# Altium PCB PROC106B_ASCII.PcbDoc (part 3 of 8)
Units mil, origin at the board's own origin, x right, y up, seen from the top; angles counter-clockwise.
Board outline 4498.18 x 1060.53 mil, 8 copper layers (Top Layer, GND1, Sig1, PWR1, PWR2, Sig2, GND2, Bottom Layer), stack 69.602 mil thick; 439 components, 327 nets, 1548 pads, 843 vias.
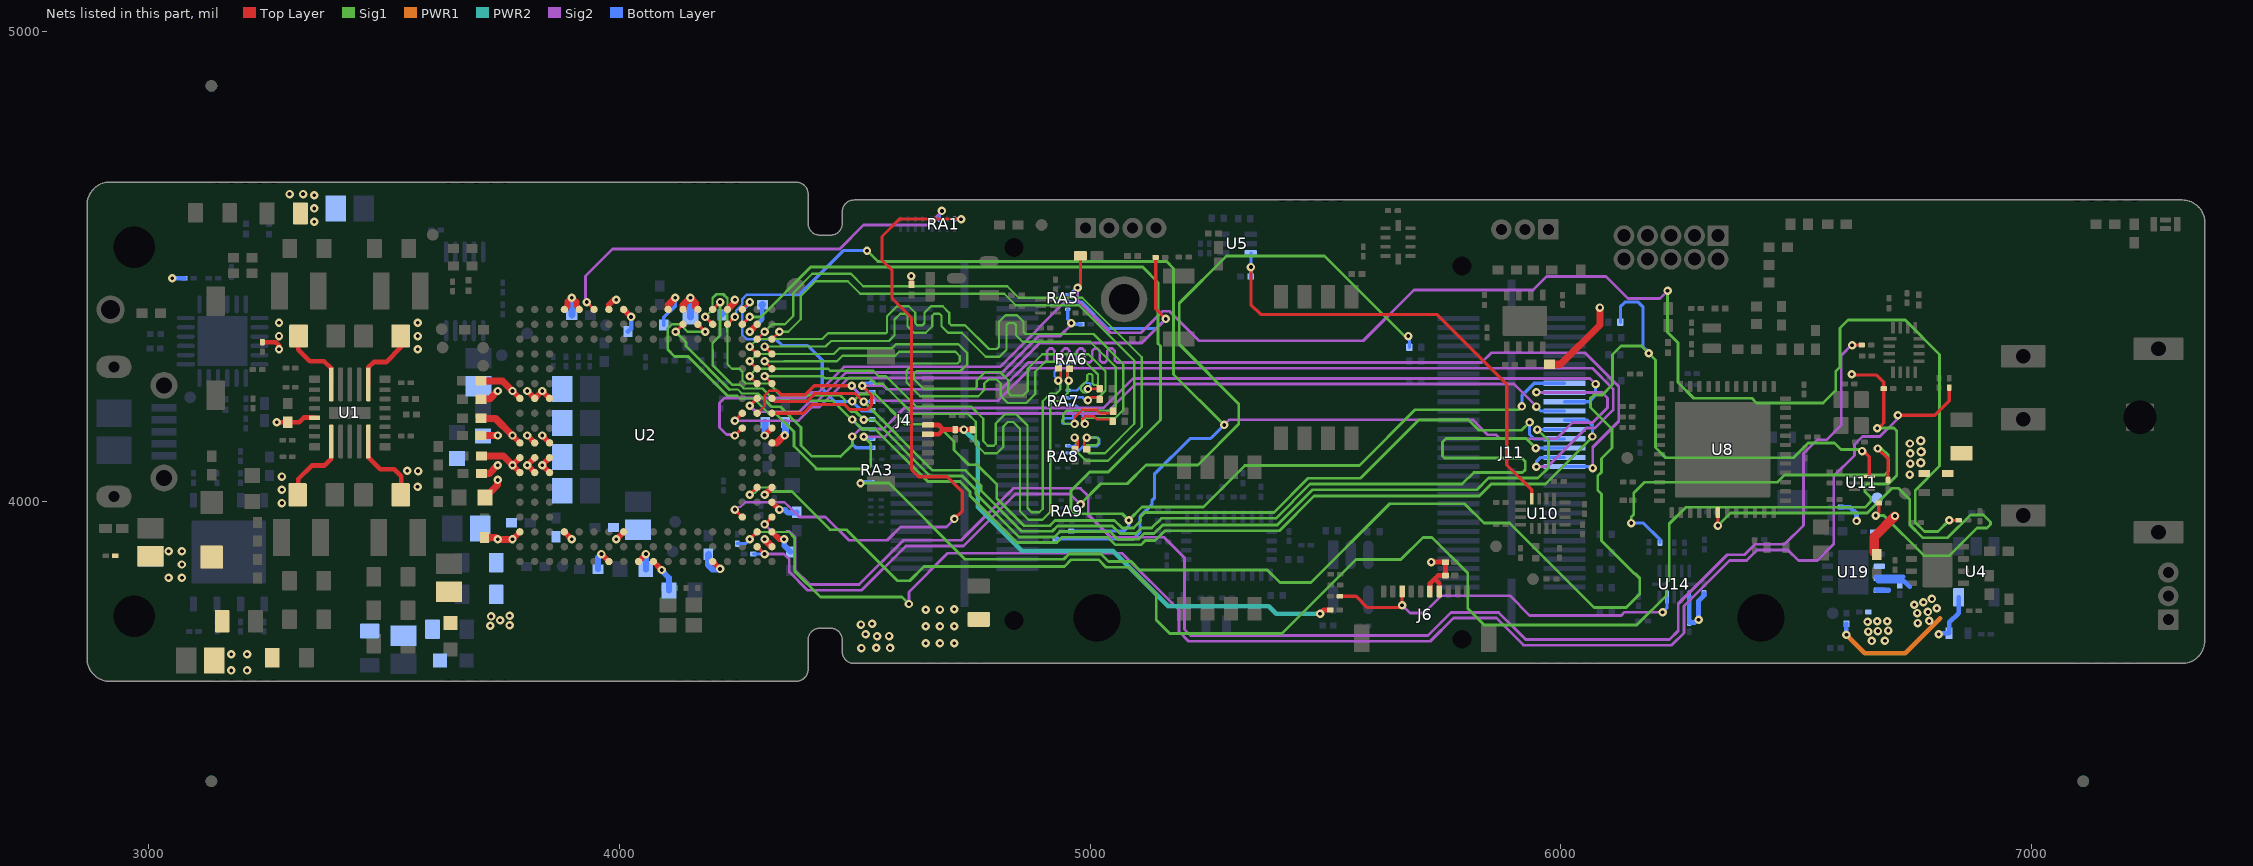
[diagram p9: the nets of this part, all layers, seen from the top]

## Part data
A1: library part CMP-0087189-1, "RF ANT 2.4GHZ CHIP SOLDER SMD"
C1 C4 C50 C51 C52 C53 C55 C59 C62 C65 C70 C76 C78 C82 C112 C113 C121: library part CMP-0008017-2, "CAP, CERM, 10 uF, 10 V, +/- 10%, X7R, 0805"
C2 C3 C91 C92 C101 C126 C130: library part CMP-0006351-2, "CAP, CERM, 0.1 uF, 16 V, +/- 10%, X7R, 0402"
C5 C11 C15 C16 C24 C115 C116 C129: library part CMP-0086446-1, "1µF ±20% 16V Ceramic Capacitor X5R 0201"
C6 C9 C10 C12 C13 C25 C26 C27 C35 C36 C37 C40 C43 C72 C86 C105 C107 C108 C109 C114 C117 C118 C119 C120 C123 C127 C128: library part CMP-0086440-1, "Cap Ceramic 0.1uF 35V X5R 10% Pad SMD 0201 85C T/R"
C7 C42 C122: library part CMP-0006339-4, "CAP, CERM, 10 uF, 10 V, +/- 20%, X5R, 0402"
C8 C125: library part CMP-0086445-1, "CAP CER 10000PF 25V X5R 0201"
C14 C71: library part CMP-0090493-1, "Cap Ceramic 4.7pF 50V C0G 0.25pF Pad SMD 0201 125°C Automotive T/R"
C17 C18: library part CMP-0086441-1, "Cap Ceramic 8pF 50V C0G 0.1pF SMD 0201 125°C Paper T/R"
C19 C20 C38 C39: library part CMP-0087190-1, "CAP CER 12PF 25V C0G/NP0 0201"
C21 C93: library part CMP-0006345-2, "CAP, CERM, 12 pF, 50 V, +/- 5%, C0G/NP0, 0402"
C22 C23 C41: library part CMP-0085178-1, "CAP, CERM, 1 pF, 50 V,+/- 25%, C0G/NP0, AEC-Q200 Grade 1, 0402"
C28 C29: library part CMP-0089043-4, "CAP CER 22UF 6.3V X5R 0402"
C30 C56 C57 C58 C60 C61 C63 C64 C66 C67 C68 C80 C81 C84 C85 C87 C88 C94 C95 C96 C97 C98: library part CMP-0078265-1, "CAP, CERM, 0.22 µF, 16 V,+/- 10%, X7R, AEC-Q200 Grade 1, 0402"
C31 C32 C33 C34: library part CMP-0085511-1, "CAP, CERM, 390 pF, 50 V,+/- 5%, C0G/NP0, AEC-Q200 Grade 1, 0402"
C44 C45 C46 C47 C48 C49 C54 C73 C75 C77 C111 C124 C131: library part CMP-0091983-1, "22µF ±20% 6.3V Ceramic Capacitor X7T 0805 (2012 Metric)"
C69: library part CMP-0006330-2, "CAP, CERM, 0.047 uF, 50 V, +/- 10%, X7R, AEC-Q200 Grade 1, 0402"
C74 C79 C83 C102 C103: library part CMP-0007134-5, "CAP, CERM, 2.2 uF, 6.3 V, +/- 10%, X7R, AEC-Q200 Grade 1, 0603"
C89 C90 C100: library part CMP-0007136-5, "CAP, CERM, 1 uF, 16 V, +/- 10%, X7R, AEC-Q200 Grade 1, 0603"
C99 C104: library part CMP-0086306-1, "CAP, CERM, 1.8 pF, 50 V,+/- 6%, C0G/NP0, 0402"
C106 C110: library part CMP-0006692-2, "CAP, CERM, 4700 pF, 50 V, +/- 10%, X7R, 0402"
D1: library part CMP-0090508-1, "Diode Schottky 30V 2A Surface Mount SOD-123FL"
FID1 FID2 FID3 FID4 FID5 FID6: library part CMP-0077181-1, "Fiducial mark.  There is nothing to buy or mount."
FL2 FL3 FL12 FL22: library part CMP-0078934-1, "Inductor, Ferrite Bead, Ferrite, 2.2 A, 0.035 ohm, AEC-Q200 Grade 1, SMD"
J1: library part CMP-0055293-1, "Connector, Receptacle, Micro-USB Type B, R/A, Bottom Mount SMT"
J2 J11: library part CMP-0075524-1, "Receptacle, 0.5 mm, 30x2, Gold, TH"
J3: library part CMP-0087187-1, "CONN HDR 1.27MM R/A AU 4POS"
J4 J6: library part CMP-0086453-1, "Easy-On™ Type FFC/FPC Connector, Right-Angle, Surface Mount, ZIF, Bottom Contact Style, 1.10mm Mated Height, 10 Circuits"
J5: library part CMP-0081851-1, "DC Power Jack, R/A, TH"
J7: library part CMP-0087786-1, "CONN HEADER R/A 10POS 1.27MM"
J8 J10: library part CMP-0087785-1, "CONN HEADER R/A 3POS 1.27MM"
L1 L6: library part CMP-0058626-1, "Inductor, Multilayer, Air Core, 2.4 nH, 0.3 A, 0.15 ohm, SMD"
L2 L3 L4 L5: library part CMP-0058944-1, "Inductor, Shielded, 470 nH, 4.7 A, 0.021 ohm, SMD"
L7: library part CMP-0062727-1, "Inductor, Multilayer, Ferrite, 6.8 uH, 0.11 A, 0.25 ohm, SMD"
L8: library part CMP-0003349-2, "Ferrite Bead, 1500 ohm @ 100 MHz, 0.5 A, 0603"
L9 L10: library part CMP-0058624-1, "Inductor, Multilayer, Air Core, 2 nH, 0.3 A, 0.1 ohm, SMD"
L11 L13 L15 L16: library part CMP-0089947-1, "100 Ohms @ 100MHz 1 Power Line Ferrite Bead 0805 (2012 Metric) 4A 20mOhm"
L12 L14: library part CMP-0077879-1, "Ferrite Bead, 120 ohm @ 100 MHz, 1.9 A, 0603"
LD1 LD2 LD3 LD4 LD5 LD6: library part CMP-0067682-2, "LED, Green, SMD"
Q1: library part CMP-0087176-1, "MOSFET N-CH 100V 170MA SOT23-3"
R1 R18 R20 R77 R78 R80 R81 R82 R93 R94 R95 R96 R98 R104 R110 R118 R122 R124 R125 R134 R177 R178: library part CMP-0088002-1, "10 kOhms ±0.5% 0.05W, 1/20W Chip Resistor 0201 (0603 Metric)  Thin Film"
R2 R28 R31 R32 R41 R60 R61 R62 R63 R103: library part CMP-0065361-1, "RES, 0, 5%, .05 W, AEC-Q200 Grade 0, 0201"
R3 R7 R8 R19 R21 R22 R23 R35 R36 R43 R44 R45 R59 R65 R83 R84 R85: library part CMP-0090084-1, "RES SMD 10K OHM 0.1% 1/20W 0201"
R4 R5 R9 R37: library part CMP-0090298-1, "100 kOhms ±1% 0.05W, 1/20W Chip Resistor 0201 (0603 Metric) Automotive AEC-Q200 Thick Film"
R6 R46 R47 R48 R49: library part CMP-0089575-2, "Res Thick Film 0201 33.2 Ohm 1% 0.05W(1/20W) ±200ppm/C Pad SMD Automotive T/R"
R10 R11 R88 R130 R132 R133 R135 R137 R138 R140: library part CMP-0087185-1, "RES SMD 20 OHM 1% 1/20W 0201"
R12 R14 R30 R51 R57 R58 R66 R67 R68 R70 R71 R72 R73 R74 R76 R86 R87 R90 R91 R97 R99 R100 R101 R102 R105 R106 R112 R113 R115 R116 R120 R121 R123 R127 R128 R129 R131 R136 R139 R142 R143 R144 R145 R146 R147 R148 R149 R150 R151 R152 R153 R154 R155 R157 R160 R161 R166 R168 R182 R183 R184 R185 R186 R187 R188 R189 R190: library part CMP-0086442-2, "RES SMD 0 OHM JUMPER 1/20W 0201"
R13 R17 R42 R111: library part CMP-0027072-1, "RES, 220, 5%, 0.05 W, 0201"
R15: library part CMP-0090501-1, "220 Ohms ±5% 0.05W, 1/20W Chip Resistor 0201 (0603 Metric) Automotive AEC-Q200 Thick Film"
R16: library part CMP-0027880-1, "RES, 7.87 k, 1%, 0.05 W, 0201"
R24: library part CMP-0087183-1, "RES SMD 200 OHM 1% 1/5W 0402"
R25 R26 R33 R34 R40 R64: library part CMP-0090497-1, "4.99 kOhms ±1% 0.05W, 1/20W Chip Resistor 0201 (0603 Metric) Automotive AEC-Q200 Thick Film"
R27 R107 R108: library part CMP-0027137-1, "RES, 510, 5%, 0.05 W, 0201"
R29 R89 R92: library part CMP-0027261-3, "RES, 100 k, 1%, 0.05 W, 0201"
R38 R69 R141: library part CMP-0027745-1, "RES, 4.99 k, 1%, 0.05 W, 0201"
R39: library part CMP-0090502-1, "510 Ohms ±5% 0.05W, 1/20W Chip Resistor 0201 (0603 Metric) Automotive AEC-Q200 Thick Film"
R50 R75: library part CMP-0090500-1, "1 kOhms ±5% 0.05W, 1/20W Chip Resistor 0201 (0603 Metric) Automotive AEC-Q200 Thick Film"
R52: library part CMP-0090496-1, "Res Thick Film 0201 1.96K Ohm 1% 1/20W 200ppm/C Molded SMD T/R"
R53 R54 R55 R56: library part CMP-0026363-2, "RES, 3.83, 1%, 0.063 W, AEC-Q200 Grade 0, 0402"
R79 R180 R181: library part CMP-0087184-1, "RESISTOR, 0201, 0.05W, 1%, 4K7"
R114 R117 R119 R126: library part CMP-0026491-2, "RES, 61.9, 1%, 0.063 W, AEC-Q200 Grade 0, 0402"
R158 R170 R172: library part CMP-0090499-1, "Res Thick Film 0201 82.5K Ohm 1% 1/20W ±200ppm/°C Molded SMD SMD T/R"
R159 R171: library part CMP-0090503-1, "Res Thick Film 0201 750 Ohm 5% 0.05W(1/20W) ±200ppm/C Pad SMD Automotive T/R"
R174 R176: library part CMP-0090498-1, "Res Thick Film 0201 7.87K Ohm 1% 1/20W ±200ppm/°C Molded SMD SMD T/R"
RA1 RA2 RA3 RA4 RA5 RA6 RA7 RA8 RA9: library part CMP-0087186-1, "RES ARRAY 4 RES ZERO OHM 0502"
S1 S2: library part CMP-0002128-2, "Switch, Slide, SPST 4 poles, SMT"
S3: library part CMP-0087181-1, "SWITCH SLIDE DIP SPST 100MA 6V"
SW2 SW3: library part CMP-0002150-2, "SWITCH TACTILE SPST-NO 0.05A 12V"
TP2 TP3 TP4 TP5 TP6 TP7 TP8 TP9 TP10 TP12 TP13 TP14 TP15 TP16 TP17 TP18 TP19 TP26 TP27 TP46: library part CMP-0078143-3, "TEST POINT.  No entry in BOM."
TP11: library part CMP-0003825-1, "1mm Test Point, SMT"
TP20: library part CMP-0086474-1, "PC Test Point, Loop Brass, Tin Plating 0.047\" (1.19mm) Hole Diameter Mounting Type"
U1: library part CMP-0079120-2, "4-A + 2.5-A + Two 1.5-A Buck Converters With Integrated Switches, RNF0026C (VQFN-HR-26)"
U2: library part CMP-0090288-2
U3: library part CMP-0087172-1, "I/O Controller Interface IC USB to Dual UART bridge"
U4: library part CMP-0035419-1, "Single Output High PSRR LDO, 200 mA, Fixed 3 V Output, 2.7 to 5.5 V Input, 5-pin SOT-23 (DBV), -40 to 85 degC, Green (RoHS & no Sb/Br)"
U5: library part CMP-0067398-2, "Automotive Grade, 1.4V-Capable +/-0.5degC Temperature Sensor with Alert Function and I2C/SMBus, DRL0006A (SOT-OTHER-6)"
U6: library part CMP-0087170-1, "8KB I2C SER EEPROM TSOT 23"
U7: library part CMP-0087171-1, "IMU ACCEL/GYRO/MAG I2C 32BIT"
U8: library part CMP-0083675-2, "SimpleLink(TM) Bluetooth(R) 5 low energy Wireless MCU, RGZ0048A (VQFN-48)"
U9: library part CMP-0079267-1, "2.3V-3.6V, 16M-BIT [x 1/x 2/x 4] CMOS FLASH Memory, WSON-8"
U10: library part CMP-0043349-1, "Low-Voltage 8-Bit I2C and SMBus I/O Expander, 1.65 to 5.5 V, -40 to 85 degC, 16-pin UQFN (RSV), Green (RoHS & no Sb/Br)"
U11: library part CMP-0050992-5, "1-Channel, 2:1 Analog Switch, DSF0006A (X2SON-6)"
U12 U17: library part CMP-0065183-3, "Automotive Fault Protected CAN Transceiver With Flexible Data-Rate, DRB0008F (VSON-8)"
U13: library part CMP-0067415-1, "10-Ohm Quad SPDT Analog Switch, RSV0016A (UQFN-16)"
U14: library part CMP-0860038-1, "Automotive 4-Bit Bidirectional Voltage-Level Translator with Auto Direction Sensing and +/-15kV ESD, RUT0012A (UQFN-12)"
U15: library part CMP-0074545-1, "Dual 10-ohm SPDT Analog Switch, RSE0010A (UQFN-10)"
U16: library part CMP-0087998-2, "AND Gate IC 1 Channel  6-SON (1x1)"
U18: library part CMP-0074341-1, "Automotive Catalog Dual 15-Ohm SPDT Analog Switch, DGS0010A (VSSOP-10)"
U19: library part CMP-0043358-3, "Dual In / Single Out Autoswitching Power Mux, 2.8 to 5.5 V, -40 to 85 degC, 8-pin SON (DRB), Green (RoHS & no Sb/Br)"
Y1: library part CMP-0090505-1, "40MHz ±10ppm Crystal 8pF 50 Ohms 4-SMD, No Lead"
Y2: library part CMP-0088076-1, "48MHz ±20ppm Crystal 7pF 50 Ohms 4-SMD, No Lead"
Y3 Y4: library part CMP-0088006-1, "CRYSTAL 32.768KHZ 4PF SMD"
ZZ1: library part CMP-0003616-3
ZZ2: library part CMP-0077236-1
ZZ3: library part CMP-0077237-1
ZZ4 ZZ5.2: library part CMP-0077238-1
ZZ5.1: library part CMP-0077238-1, "Cut the thermal pad(Part Number#GPVOUS-0.125-AC-0816) for the shape and size of the inner surface of the heatsink(Part Number#160018120021) and paste it on the inner surface of the heatsink;"

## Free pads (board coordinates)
  round 19 hole 24 unplated: ""(3145.41,4687.43) ""(3145.41,3610.9) ""(3175.41,4687.43) ""(3175.41,3610.9) ""(3205.41,4687.43) ""(3205.41,3610.9) ""(3235.41,4687.43) ""(3235.41,3610.9) ""(3265.41,4687.43) ""(3265.41,3610.9) ""(3637.19,4687.43) ""(3637.19,3610.9) ""(3667.19,4687.43) ""(3667.19,3610.9) ""(3697.19,4687.43) ""(3697.19,3610.9) ""(3727.19,4687.43) ""(3727.19,3610.9) ""(3757.19,4687.43) ""(3757.19,3610.9) ""(4128.97,3610.9) ""(4128.97,4687.43) ""(4158.97,3610.9) ""(4158.97,4687.43) ""(4188.97,4687.43) ""(4188.97,3610.9) ""(4218.97,3610.9) ""(4218.97,4687.43) ""(4248.97,3610.9) ""(4248.97,4687.43) ""(4646.5,3648.05) ""(4676.5,3648.05) ""(4706.5,3648.05) ""(4736.5,3648.05) ""(4766.5,3648.05) ""(5409.11,4649.48) ""(5439.11,4649.48) ""(5469.11,4649.48) ""(5499.11,4649.48) ""(5529.11,4649.48) ""(5950.52,3648.05) ""(5980.52,3648.05) ""(6010.52,3648.05) ""(6040.52,3648.05) ""(6070.52,3648.05) ""(7097.6,3648.05) ""(7097.68,4649.43) ""(7127.6,3648.05) ""(7127.68,4649.43) ""(7157.6,3648.05) ""(7157.68,4649.43) ""(7187.6,3648.05) ""(7187.68,4649.43) ""(7217.6,3648.05) ""(7217.68,4649.43)

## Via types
v1: diameter 18, hole 8, Top Layer to Bottom Layer, tented both sides, 804 vias
v2: diameter 19.68, hole 7.87, Top Layer to Bottom Layer, tented both sides, 34 vias
v3: diameter 20, hole 10, Top Layer to Bottom Layer, tented both sides, 3 vias
v4: diameter 18, hole 8, Top Layer to Bottom Layer, 1 vias
v5: diameter 17, hole 7.87, Top Layer to Bottom Layer, 1 vias

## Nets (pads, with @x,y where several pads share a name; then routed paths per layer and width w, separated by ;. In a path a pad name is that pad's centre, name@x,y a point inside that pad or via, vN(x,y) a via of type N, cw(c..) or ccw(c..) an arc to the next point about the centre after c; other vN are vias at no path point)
3V0: C7.1 C15.1 C16.1 C115.1 C116.1 C118.1 J4.6 J4.7 J6.6 J6.7 R79.2 R181.2 U4.5 U14.1 | length 1553.4
  Top Layer w10: J4.7@4655.33,4143.81 4678.32,4143.81 4688.3,4153.79 ; J4.6@4655.33,4163.49 4678.59,4163.49 4688.3,4153.79 ; C15.1@4750.21,4153.69 4750.12,4153.79 v1(4731.8,4153.79) C16.1@4713.47,4153.79 4688.3,4153.79 ; v1(5488.42,3762.4) 5496.67,3770.65 R181.2@5510.03,3770.65 ; J6.6@5721.75,3810.06 5721.75,3826.54 5731.98,3836.77 ; v1@5724.8,3872.26 5724.87,3872.2 C115.1@5754.85,3872.2 C116.1@5754.85,3843.74 5738.95,3843.74 5731.98,3836.77 ; J6.7@5741.43,3807.06 5741.43,3827.32 5731.98,3836.77
  PWR2 w10: v1(4731.8,4153.79) 4761,4124.58 4761,3989.4 4854.25,3896.15 5048.17,3896.15 5165.74,3778.57 5379.01,3778.57 5395.18,3762.4 v1(5488.42,3762.4)
  Bottom Layer w10: U14.1@6272.54,3799.77 6272.54,3764.35 6272.5,3764.32 C118.1@6272.5,3743.88 6284.34,3743.88 6292.44,3751.98 6292.44,3789.79 6304.11,3801.46 R79.2@6304.11,3805.64 ; v1(6802.79,3718.79) 6804.79,3720.79 C7.1@6824.78,3720.79 6824.78,3743.97 6844.78,3763.97 U4.5@6844.78,3797.49
  other v1: 6292.44,3749.79 5724.6,3872.26
5V_HD_IN: C128.1 L16.2 R20.1 U19.8 | length 78.8
  Bottom Layer w10: R20.1@6594.7,3988.94 6614.05,3988.94 6628.05,3974.95 v1(6628.05,3959.58)
  Bottom Layer w12: U19.8@6671.07,3812.08 6695.37,3812.08
  other v1: 4650.94,3699.61 4681.04,3699.61 4711.61,3699.61 6660.22,3704.68 6688.14,3705.36 6652.66,3724.54 6673.29,3725.69 6695.37,3726.86 4650.94,3735.76 4681.04,3735.76 4711.61,3735.76 6651.3,3745.4 6671.76,3746.63 6693.22,3746.68 4650.93,3770.89 4681.04,3771.4 4711.61,3772.13
5V_IN: C1.2 C4.1 C30.1 C50.1 C51.1 C52.1 C53.1 C129.1 D1.1 FL3.2 FL12.2 R27.1 R39.1 R50.2 R64.1 R107.1 U1.9 U1.13 U1.18 U1.22 U1.26 U19.7 | length 1553.7
  Top Layer w10: R50.2@3241.63,4339.44 3270.32,4339.44 3277.02,4332.74 v1@3277.02,4326.81 ; v1(3272.33,4169.32) C30.1@3295.87,4169.32 3319.81,4169.32 3329.65,4179.16 U1.18@3352.68,4179.16 ; C50.1@3318.11,4009.52 3318.11,4048.7 3346.62,4077.21 3373.07,4077.21 3388.04,4092.18 ; C52.1@3318.11,4368.48 3318.11,4323.58 3342.64,4299.04 3372.63,4299.04 3388.11,4283.56 U1.13@3388.11,4249.63 ; 3388.11,4092.18 U1.22@3388.11,4128.37 ; U1.26@3466.85,4128.37 3466.85,4094.45 3492.01,4069.29 3521.99,4069.29 3536.85,4054.43 C51.1@3536.85,4009.52 ; U1.9@3466.85,4249.63 3466.85,4285.9 3478.07,4297.12 3504.66,4297.12 3536.85,4329.31 C53.1@3536.85,4368.48 ; v1(4620.27,4479.75) 4620.57,4479.46 R107.1@4620.57,4461.7
  Top Layer w15: FL12.2@5975.6,4292.41 5999,4292.41 6082.75,4376.16 v1(6082.75,4412.79)
  Top Layer w20: FL3.2@6670.79,3888.25 6665.81,3893.23 6665.81,3926.17 v5(6709.55,3969.91)
  PWR1 w10: v1(6606.39,3717.68) 6645.55,3678.52 6731.31,3678.52 6805.46,3752.67
  Bottom Layer w10: v1(3050.47,4475.15) R64.1@3076.13,4475.15 ; v1(6606.39,3717.68) R27.1@6606.39,3741.52 ; U19.7@6673.76,3836.69 6698.11,3836.69 6703.21,3831.6 ; 6711.81,3839.4 6710.11,3841.1 ; 6726.91,3841.1 6710.11,3841.1 ; 6740.73,3819.94 6729.08,3831.6 6703.21,3831.6 ; 6703.21,3831.6 6673.82,3831.6 6669.11,3840.2 6670.01,3841.1 6710.11,3841.1
  other v1: 4514.3,3689.55 4545.9,3690.22 4574.96,3689.89 4547.43,3714.8 4572.89,3715.13 4522.96,3718.74 4513.24,3739.55 4536.9,3741.13 6757.93,3742.77 6782.31,3747.33 6756.77,3763.83 6779.56,3766.42 6798.43,3774.05 6750.69,3781.76 6770.14,3787.01 6788.19,3794.02 3042.55,3838.89 3070.75,3838.89 3070.75,3867.09 3042.55,3895.28 3070.75,3895.28 3283.23,3997.47 3283.23,4025.66 3571.45,4032.48 3283.23,4053.86 3549.23,4066.35 3572.38,4065.53 3277.02,4324.15 3571.73,4324.15 3277.02,4352.35 3571.73,4352.35 3277.02,4380.54 3571.73,4380.54
5V_IN_B: C42.2 C122.1 C127.1 L15.2 TP4.1 U19.6
  other v1: 6741.2,4058 6741.81,4081.54 6741.81,4103 6741.32,4124.11
  other v3: 6764.6,4082.97 6765.01,4106.67 6764.46,4130
ALERT: R38.1 U5.3 U10.4 | length 1009.2
  Top Layer w6.7: v1(5341.5,4498.97) 5341.5,4418.98 5362.14,4398.33 5736.3,4398.33 5885.05,4249.58 5885.05,4078.41 5937.93,4025.53 U10.4@5937.93,4006.69
  Bottom Layer w6.7: R38.1@5341.5,4478.82 v1(5341.5,4498.97) U5.3@5341.5,4529.03 U5.3@5341.84,4528.69
AR_1P0_RF1: C75.2 C78.1 C79.1 C80.1 C81.1 C113.1 C124.2 L12.2 U2.J16 U2.J17 U2.J18 | length 184.7
  Top Layer w12: v1(3773.02,4141.13) U2.J18@3788.76,4125.38 ; v1(3804.51,4141.13) U2.J17@3820.26,4125.38 ; v1(3836.01,4141.13) U2.J16@3851.76,4125.38
  Top Layer w15: C80.1@3705.88,4141.13 v1(3741.52,4141.13) ; C81.1@3705.88,4177.66 3736.48,4177.66 v1(3773.02,4141.13)
  other v1: 3725.88,3737.02 3766.78,3737.9 3746.66,3748.61 3727.42,3756.7 3766.78,3758.45
AR_1P0_RF2: C70.1 C74.1 C82.1 C83.1 C84.1 C85.1 C111.2 C121.1 C131.2 L14.2 U2.G16 U2.G17 U2.G18 U2.H16 U2.H17 U2.H18 | length 297.2
  Top Layer w12: U2.G18@3788.76,4062.39 v1(3773.02,4078.14) U2.H18@3788.76,4093.88 ; U2.G17@3820.26,4062.39 v1(3804.51,4078.14) U2.H17@3820.26,4093.88 ; U2.G16@3851.76,4062.39 v1(3836.01,4078.14) U2.H16@3851.76,4093.88
  Top Layer w15: C84.1@3707.42,4060.46 3723.84,4060.46 v1(3741.52,4078.14) ; C85.1@3707.42,4097.51 3753.64,4097.51 v1(3773.02,4078.14) ; C74.1@3714.74,4009.15 3741.52,4035.93 v1(3741.52,4046.64)
AR_1P2: C76.1 C91.2 C92.2 C94.1 C95.1 C96.1 C97.1 C98.1 C103.1 L13.2 U2.A5 U2.C1 U2.E1 U2.J1 U2.V4 U2.V6 U2.V7 U2.V8 U2.V12 U2.V14 U2.V15 | length 667.8
  Top Layer w12: U2.V15@3883.25,4408.84 3890,4415.59 3890,4425.59 3899,4434.59 3909,4424.59 3909,4417 3914.75,4411.25 U2.V14@3914.75,4408.84 ; U2.V12@3977.74,4408.84 3977.74,4418.84 3988.49,4429.59 v1(3993.49,4429.59) ; U2.A5@4198.21,3873.41 v1(4213.96,3857.66) ; U2.C1@4324.2,3936.4 4339.94,3920.65 v1(4349.94,3920.65) ; U2.E1@4324.2,3999.4 4324.33,3999.4 v1(4340.08,3983.65)
  Top Layer w15: U2.V8@4103.72,4408.84 4103.72,4418.45 v1(4118.96,4433.68) ; U2.V7@4135.22,4408.84 4135.22,4417.93 v1(4150.97,4433.68) 4161.76,4422.88 4161.76,4413.8 U2.V6@4166.72,4408.84 ; U2.V4@4229.71,4408.84 4245.46,4424.59 v1(4245.46,4429.68) ; U2.J1@4324.2,4125.38 4334.2,4125.38 v1@4350.05,4141.24
  Bottom Layer w8: C96.1@4094.31,4375.82 4094.31,4392.25 4118.96,4416.91 v1(4118.96,4433.68)
  Bottom Layer w10: v1@3898.96,4434.55 v1@3899,4434.59 ; v1(4150.97,4433.68) v1@4150.97,4434.59
  Bottom Layer w12: C91.2@4218.02,4397.33 4245.46,4424.77 v1(4245.46,4429.68) ; v1(4340.08,3983.65) 4351.45,3983.65 4358.24,3976.86 4375.3,3976.86 C95.1@4376.53,3978.09 ; v1@4350,3920 4350,3908 C94.1@4364,3894
  Bottom Layer w15: C98.1@3898.96,4396.76 v1@3898.96,4434.55 ; C103.1@4150.97,4392.63 v1(4150.97,4433.68) ; C97.1@4188.97,3888.79 4189.39,3888.36 4189.39,3866.45 4198.18,3857.66 v1(4213.96,3857.66) ; v1@4350.05,4141.24 4352.69,4143.87 C92.2@4352.69,4168.77
  other v1: 4351.25,4141.24 3899,4433.68 3352.15,4595.26 3352.15,4623.45 3352.15,4651.65 3299.59,4653.99 3328.09,4653.99
AR_1V4_APLL: C90.1 U2.A10 | length 56.1
  Top Layer w12: U2.A10@4040.73,3873.41 v1(4056.48,3889.16)
  Bottom Layer w10: C90.1@4056.23,3855.43 C90.1@4056.48,3855.68
  Bottom Layer w12: C90.1@4056.48,3855.68 v1(4056.48,3889.16)
AR_1V4_SYNTH: C89.1 U2.A9 | length 72
  Top Layer w12: U2.A9@4072.23,3873.41 v1@4087.98,3857.66
  Bottom Layer w12: v1(4090.2,3855.43) 4090.2,3853.81 4105.41,3838.6 C89.1@4105.41,3811.96
AR_1V8: C55.1 C56.1 C57.1 C58.1 C59.1 C60.1 C61.1 C62.1 C63.1 C64.1 C65.1 C66.1 C67.1 C68.1 C73.2 C112.1 L11.2 U2.A12 U2.B1 U2.C11 U2.C15 U2.C18 U2.F1 U2.K1 U2.M16 U2.M17 U2.M18 U2.U2 U2.V11 | length 635.6
  Top Layer w12: v1(3773.02,3920.65) U2.C18@3788.76,3936.4 ; v1(3773.02,4235.62) U2.M18@3788.76,4219.87 ; v1(3804.51,4235.62) U2.M17@3820.26,4219.87 v1(3836.01,4235.62) U2.M16@3851.76,4219.87 ; U2.C15@3883.25,3936.4 v1(3899,3920.65) ; v1(3961.99,3889.16) U2.A12@3977.74,3873.41 ; v1(3993.49,3920.66) U2.C11@4009.24,3936.4 ; U2.V11@4009.24,4408.84 v1(4024.98,4393.1) ; v1(4276.95,4361.6) U2.U2@4292.7,4377.35 ; v1(4308.45,4015.14) U2.F1@4324.2,4030.89 ; v1(4308.45,4141.13) U2.K1@4324.2,4156.88
  Top Layer w15: C58.1@3705.86,4218.19 3724.1,4218.19 v1(3741.52,4235.62) ; C57.1@3705.86,4257.19 3751.44,4257.19 v1(3773.02,4235.62) ; C68.1@3713.57,3924.11 3738.07,3924.11 v1(3741.52,3920.65) v1(3773.02,3920.65) ; v1(4308.45,3920.65) U2.B1@4324.2,3904.91
  Bottom Layer w10: C61.1@4018.33,4361.9 4024.98,4368.55 v1(4024.98,4393.1) ; v1(4276.95,4361.6) 4303.38,4388.02 C56.1@4303.38,4418.18 ; v1(4308.45,4141.13) v1@4309.75,4142.43
  Bottom Layer w12: C63.1@3954.76,3856.83 3954.76,3881.92 v1(3961.99,3889.16)
  Bottom Layer w15: C56.1@4303.38,4418.18 C56.1@4304.26,4419.07 ; v1@4309.75,4142.43 C60.1@4309.75,4168.77
  other v1: 3175.57,3642.06 3209.12,3642.06 3175.57,3676.64 3209.12,3676.64
AR_BSS_LOGGER: RA1.4 U2.D3 | length 1457.8
  Top Layer w6.7: v1(4245.46,3983.65) U2.D3@4261.2,3967.9 ; v1(4711.71,3963.9) 4728.31,3980.49 4728.31,4021.77 4696.67,4053.41 4635.8,4053.41 4620.6,4068.61 4620.6,4390.98 4579.49,4432.09 4579.49,4491.76 4557.8,4513.46 4557.8,4563.91 4594.61,4600.72 4725.6,4600.72 v1(4725.75,4600.58)
  Sig2 w4.5: v1(4245.46,3983.65) 4250.76,3988.95 4256.7,3988.95 4267.15,3999.4 4350.75,3999.4 4358.91,3991.23
  Sig2 w5.95: 4358.91,3991.23 4382.26,3967.89 4438.09,3967.89 4487.48,3918.5 4569.04,3918.5 4597.24,3946.7 4694.51,3946.7 v1(4711.71,3963.9)
  Bottom Layer w6.7: RA1.4@4711.71,4600.58 v1(4725.75,4600.58)
AR_CS1: R9.2 R139.2 U2.C2 | length 3317
  Top Layer w6.7: v1(4276.95,3920.66) U2.C2@4292.7,3936.4 ; v1(6715.81,4184) 6794.11,4184 6824.81,4214.7 R139.2@6824.81,4242.98
  Sig1 w4.5: v1(4276.95,3920.66) 4292.55,3936.25 ; 4292.57,3936.4 4359.48,3936.4 4367.2,3928.68
  Sig1 w5.95: 4367.2,3928.68 4372.68,3923.2 4372.68,3852.89 4427.56,3798 4600.39,3798 v1(4615.19,3783.2)
  Sig2 w5.95: v1(4615.19,3783.2) 4615.19,3808.93 4697.19,3890.93 5068.04,3890.93 5188.57,3770.4 5188.57,3724.39 5208.81,3704.15 5722.57,3704.15 5771.73,3753.31 5862.89,3753.31 5920.43,3695.78 6235.45,3695.78 6261.24,3721.57 6261.24,3778.92 6358.17,3875.85 6394.55,3875.85 6416.88,3898.18 6481.96,3898.18 6504.38,3875.76 6544.85,3875.76 6579.54,3910.44 6579.54,4054.9 6623.31,4098.68 6623.31,4121.75 6640.56,4138.99 6677.31,4138.99 6715.81,4177.5 v1(6715.81,4184)
  Bottom Layer w6.7: R9.2@4250.53,3911.55 4267.85,3911.55 v1(4276.95,3920.66)
AR_CS1_60PIN: R150.2 RA3.1 U11.3 | length 3577.1
  Top Layer w6.7: v1@6639.79,4111.11 6655.07,4095.82 U11.3@6655.07,4054.07
  Sig1 w5.95: v1(4512.23,4039.9) 4572.79,4039.9 4734.57,3878.13 4943.97,3878.13 4955.07,3889.24 5022.69,3889.24 5038.76,3873.16 5087.38,3873.16 5105.13,3855.41 5376.27,3855.41 5403.06,3828.62 5468.8,3828.62 5636.32,3996.14 5795.11,3996.14 5836.32,3954.93 5891.16,3954.93 6070.18,3775.91 6138.83,3775.91 6167.52,3804.59 6167.52,3837.84 6157.87,3847.49 6156.34,3847.49 6086.26,3917.56 6086.26,4017.07 6078.05,4025.28 6078.05,4054.78 6086.26,4062.99 6086.26,4092.5 6108.35,4114.59 6108.35,4155.16 6062.88,4200.64 6062.88,4220.16 6069.96,4227.25 6087.72,4227.25 6109.66,4249.18 6109.66,4313.09 6127.8,4331.24 6171.18,4331.24 v1(6186.75,4315.67) 6200.65,4301.78 6200.65,4115.91 6222.76,4093.79 6494.18,4093.79 6525.34,4124.95 6581.02,4124.95 6594.86,4111.11 v1@6639.79,4111.11
  Bottom Layer w6.7: v1(4512.23,4039.9) 4513.87,4039.9 4517.57,4043.61 RA3.1@4535.95,4043.61 ; R150.2@6126.41,4381.76 6126.41,4414.59 6136.18,4424.36 6164.48,4424.36 6174.21,4414.64 6174.21,4330.28 6186.75,4317.73 v1(6186.75,4315.67)
  other v1: 6639.79,4107.91
AR_CS1_BT: R105.2 U8.30 | length 1081.1
  Top Layer w6.7: v1(6333.54,3949.8) U8.30@6333.54,3977.25 ; v1(6668.81,3971.01) 6675.01,3977.22 R105.2@6675.01,3997.34
  Sig1 w5.95: v1(6333.54,3949.8) 6360.37,3976.64 6650.73,3976.64 6703.16,4029.07 6717.11,4029.07 6740.89,4005.29 6740.89,3951.61 6768.42,3924.08 6821.79,3924.08 6869.97,3972.26 6897.81,3972.26 6912.48,3957.59 6912.48,3951.77 6905.1,3944.39 6884.07,3944.39 6825.56,3885.88 6770.99,3885.88 6685.86,3971.01 v1(6668.81,3971.01)
AR_CS1_LCD: R76.2 R106.2 | length 847.6
  Top Layer w6.7: v1(6673.04,4113.48) 6673.04,4113.33 6695.04,4091.34 R106.2@6695.04,4046.53
  Sig1 w5.95: v4(6149.58,3955.16) 6149.58,3967.73 6154.54,3972.7 6154.54,4018.54 6178,4042 6459.94,4042 6475.03,4057.09 6687.59,4057.09 6695.45,4064.95 6695.45,4099.24 6681.21,4113.48 v1(6673.04,4113.48)
  Bottom Layer w6.7: v4@6150.63,3956.21 v4(6149.58,3955.16) 6174.89,3955.16 6210.78,3919.27 R76.2@6210.78,3913.46
AR_CS1_LCD_T: J6.3 R183.1 U14.4 | length 808.1
  Top Layer w6.7: R183.1@5530.62,3799.62 5564.89,3799.62 5589,3775.51 5662.69,3775.51 v1(5662.69,3780.5) J6.3@5662.69,3810.06
  Sig2 w5.95: v1(5662.69,3780.5) 5679.39,3763.8 5708.98,3763.8 5746.07,3800.89 5891.53,3800.89 5933.37,3759.05 6128.25,3759.05 6135,3765.81 v1(6215.84,3765.81)
  Bottom Layer w6.7: v1(6215.84,3765.81) 6225.29,3775.26 U14.4@6225.29,3797.8
AR_DMM_CLK: J11.15 R11.1 U2.U3 | length 2863.5
  Top Layer w6.7: U2.U3@4261.2,4377.35 v1(4276.95,4393.1)
  Sig1 w5.95: v1(4276.95,4393.1) 4300.77,4393.1 4406.49,4498.81 5111.66,4498.81 5144.37,4466.1 5144.37,4336.15 5149.25,4331.27 5149.25,4174.31 5038.48,4063.54 4999.25,4063.54 4959.53,4023.82 4959.53,3983.93 4968.69,3974.76 5068.35,3974.76 v1(5082.11,3961) 5110.48,3989.37 5240.5,3989.37 5328.59,4077.46 5572.06,4077.46 5690.34,4195.73 5910.11,4195.73 v1(5917.11,4202.74)
  Bottom Layer w6.7: R11.1@4960.02,3937.94 5071.27,3937.94 5082.11,3948.78 v1(5082.11,3961) ; v1(5917.11,4202.74) 5917.11,4225.75 5943.5,4252.14 J11.15@6007.91,4252.14
AR_DMM_SYNC: J11.17 R10.1 U2.U4 | length 3035.4
  Top Layer w6.7: U2.U4@4229.71,4377.35 v1(4245.46,4393.1)
  Sig1 w5.95: v1(4526.01,4533.75) 4549.05,4510.71 5162.64,4510.71 5177.31,4496.03 5177.31,4270.93 v1(5284.75,4163.49)
  Sig2 w5.95: v1(5284.75,4163.49) 5296,4174.75 5811.84,4174.75 5843.88,4142.71 5862.4,4142.71 5871.08,4134.03 5990.13,4134.03 6024.74,4168.63 6067.55,4168.63 6099.07,4200.15 6099.07,4221.06 6087.61,4232.53 5948.46,4232.53 v1(5947.91,4233.07)
  Bottom Layer w5: v1(4245.46,4393.1) 4247.94,4395.58 4247.94,4406.09 4261.2,4419.35 4261.2,4430.66 4261.25,4430.71 4261.25,4431.1 4270.45,4440.29 4287.98,4440.29 4382.34,4440.31 4385,4442.97
  Bottom Layer w5.5: J11.17@6007.91,4232.45 J11.17@6008.02,4232.56
  Bottom Layer w6.7: 4385,4442.97 4475.78,4533.75 v1(4526.01,4533.75) ; R10.1@4927.02,3921 5090.97,3921 5106.23,3936.25 5106.23,3969.32 5131.09,3994.18 5131.09,4002.21 5136.5,4007.62 5136.5,4058.65 5212.51,4134.66 5255.92,4134.66 v1(5284.75,4163.49) ; v1@5946.67,4229.5 v1@5947.91,4230.74 ; v1(5947.91,4233.07) v1@5947.91,4230.74 ; J11.17@6007.91,4232.45 5949.62,4232.45 v1@5947.91,4230.74
AR_DP0: J11.19 R88.1 U2.U7 | length 2348.9
  Top Layer w6.7: v1(4119.47,4361.6) U2.U7@4135.22,4377.35
  Sig1 w4.5: 4233.93,4238.41 4252.3,4238.41 4260.24,4230.47 4294.69,4230.47
  Sig1 w5.95: v1(4119.47,4361.6) 4141.45,4339.62 4141.45,4330.89 4233.93,4238.41 ; 4295.71,4229.45 4323.07,4202.09 4342.27,4202.09 4385.89,4158.47 4385.89,4120.26 4409.3,4096.84 4469.39,4096.84 4469.78,4096.45 4494.9,4121.58 v1(4494.9,4138.98)
  Sig2 w5.95: v1(4494.9,4138.98) 4511.03,4155.1 4560.94,4155.1 4605.25,4199.42 5028.67,4199.42 5091.43,4262.18 6061.63,4262.18 v1(6073.52,4250.28)
  Bottom Layer w6.7: v1@4494.9,4134.98 4494.9,4123.11 4503.04,4114.97 R88.1@4537.25,4114.97 ; J11.19@6007.91,4212.77 6060.26,4212.77 6073.52,4226.03 v1(6073.52,4250.28)
AR_DP1: J11.21 R130.1 U2.U6 | length 2360.1
  Top Layer w6.7: U2.U6@4166.72,4377.35 v1(4182.46,4361.6)
  Sig1 w4.5: 4103,4368.42 4111.93,4377.35 4128.99,4377.35 4144.74,4361.6 v1(4182.46,4361.6) ; 4229.91,4225.61 4250.33,4225.61 4255.92,4220.03 4284.86,4220.03 4316.74,4188.14
  Sig1 w5.95: 4103,4368.42 4103,4323.28 4117.2,4309.08 4146.44,4309.08 4229.91,4225.61 ; 4316.74,4188.14 4331.88,4188.14 4370.86,4149.16 4370.86,4118.46 4417.54,4071.79 4417.54,4069.92 4526.78,4069.92 4534.17,4077.3 4534.17,4123.47 v1(4519,4138.63)
  Sig2 w5.95: v1(4519,4138.63) 4564,4138.63 4612.89,4187.52 5033.59,4187.52 5096.35,4250.28 5900.26,4250.28 v1(5947.9,4202.64)
  Bottom Layer w6.7: v1@4519,4134.63 R130.1@4537.25,4134.63 ; v1(5947.9,4202.64) 5957.46,4193.08 J11.21@6007.91,4193.08
AR_DP2: J11.23 R132.1 U2.V5 | length 2435.9
  Top Layer w5.5: v1(4213.96,4424.59) v1@4214.41,4425.04
  Top Layer w6.7: U2.V5@4198.21,4408.84 v1(4213.96,4424.59)
  Sig1 w4.5: 4198.21,4322.56 4198.21,4336.63 4198.21,4337.65 ; 4240.31,4248.86 4256.63,4248.86 4264.57,4240.92 4304.42,4240.92
  Sig1 w5.95: 4198.21,4322.56 4198.21,4290.95 4239.58,4249.58 ; 4198.21,4337.65 4213.96,4353.4 v1(4213.96,4424.59) ; 4305.18,4240.16 4330.57,4214.77 4453.46,4214.77 4488.56,4179.67 4490.32,4179.67 v1(4494.9,4175.09) 4514.89,4155.1 4543.36,4155.1 4655.16,4043.31 4723.42,4043.31 4745.07,4021.66 4745.07,4013.15 4844.29,3913.93 4929.3,3913.93 4940.54,3925.16 5037.22,3925.16 5053.54,3908.85 5107.85,3908.85 5117.16,3918.16 5137.98,3918.16 5158.66,3938.83 5402.06,3938.83 5475.84,4012.61 5826.59,4012.61 5852.07,4038.09 5966.94,4038.09 6066.87,4138.03 v1(6066.87,4138.99)
  Bottom Layer w6.7: v1(4494.9,4175.09) 4514.56,4155.43 R132.1@4537.25,4155.43 ; J11.23@6007.91,4173.4 6056.48,4173.4 6066.87,4163.01 v1(6066.87,4138.99)
AR_DP3: J11.25 R133.1 U2.U5 | length 2407.4
  Top Layer w6.7: v1(4182.46,4393.1) U2.U5@4198.21,4377.35
  Sig1 w4.5: v1(4182.46,4393.1) 4198.21,4408.84 4198.21,4433.25 ; 4228.98,4361.6 4229.71,4360.88 4229.71,4292.08 4238.93,4282.86 4255.66,4282.86 4255.66,4282.75 4261.2,4277.2 4261.2,4259.06 4268.9,4251.36 4318.19,4251.36 ; 4228.98,4431.84 4228.98,4432.86 ; 4229.71,4411.06 4229.71,4433.15
  Sig1 w5.95: 4198.21,4433.25 4206.03,4441.06 4220.78,4441.06 4228.98,4432.86 ; 4228.98,4361.6 4228.98,4411.06 ; 4318.19,4251.36 4342.89,4226.67 4469.05,4226.67 4478.43,4217.29 4478.43,4206.63 4493.49,4191.56 4502.18,4191.56 v1(4519,4174.75) 4540.54,4174.75 4660.08,4055.2 4728.34,4055.2 4756.96,4026.58 4756.96,4018.07 4849.21,3925.82 4924.38,3925.82 4935.61,3937.06 5042.15,3937.06 5058.47,3920.74 5102.48,3920.74 5114.37,3932.63 5135.64,3932.63 5154.16,3951.16 5397.56,3951.16 5472.3,4025.89 5821.67,4025.89 5846.41,4050.63 5951.35,4050.63 5973.44,4072.73 5973.44,4130.25 v1(5949.98,4153.71)
  Bottom Layer w6.7: v1(4519,4174.75) R133.1@4537.25,4174.75 ; v1(5949.98,4153.71) J11.25@6007.91,4153.71
AR_DP4: J11.27 R135.1 U2.V3 | length 2293.3
  Top Layer w6.7: U2.V3@4261.2,4408.84 v1(4276.95,4424.59)
  Sig1 w5.95: v1(4494.9,4213.45) 4496.05,4213.45 4512.18,4229.58 4542.79,4229.58 4607.41,4164.95 4674.82,4164.95 4711.09,4128.67 4711.09,4110.12 4742.23,4078.99 4759.45,4078.99 4801.8,4036.65 4801.8,4006.88 4859.07,3949.61 4914.52,3949.61 4925.76,3960.85 5052,3960.85 5068.32,3944.53 5092.48,3944.53 5106.35,3958.4 5106.35,3967.82 5116,3977.47 5390.24,3977.47 5463.1,4050.33 5574.33,4050.33 5698,4174 5804,4174 5825.87,4152.13 5916.56,4152.13 v1(5933.38,4168.95)
  Bottom Layer w5: v1@4276.95,4419.75 4261.2,4404.01 4261.2,4355.5 4261.2,4355.08 4270.43,4345.85 4316.17,4345.85
  Bottom Layer w6.7: 4316.17,4345.85 4332.22,4345.85 4345.89,4332.18 4399.87,4332.18 4430.97,4301.09 4430.97,4240.33 4457.85,4213.45 v1(4494.9,4213.45) 4514.56,4193.79 R135.1@4537.25,4193.79 ; v1(5933.38,4168.95) 5933.38,4143.54 5942.89,4134.03 J11.27@6007.91,4134.03
AR_DP5: J11.29 R137.1 U2.M1 | length 2321.9
  Top Layer w6.7: U2.M1@4324.2,4219.87 4331.08,4212.98 4398.06,4212.98 4415.2,4230.12 4501.7,4230.12 4518.72,4213.1 v1(4519,4213.1)
  Sig1 w5.95: v1(4519,4213.1) 4665.01,4067.1 4735.13,4067.1 4768.85,4033.38 4768.85,4023 4854.14,3937.72 4919.45,3937.72 4930.69,3948.95 5047.08,3948.95 5063.39,3932.63 5097.55,3932.63 5109.44,3944.53 5130.71,3944.53 5151.36,3965.17 5394.76,3965.17 5467.37,4037.79 5790.28,4037.79 5815.02,4062.53 5918.43,4062.53 5924.37,4068.47 5924.37,4085.74 5917.05,4093.05 5752.9,4093.05 5748.41,4097.55 5748.41,4127.01 5756.06,4134.66 5926.35,4134.66 v1(5946.67,4114.34)
  Bottom Layer w6.7: v1(4519,4213.1) R137.1@4537.25,4213.11 ; v1(5946.67,4114.34) J11.29@6007.91,4114.34
AR_DP6: J11.31 R138.1 U2.L2 | length 2306.4
  Top Layer w5: U2.L2@4292.7,4188.37 4308.82,4204.49 4308.82,4226.24 4318.58,4235.99 4335.56,4235.99
  Top Layer w6.7: 4335.56,4235.99 4343.78,4227.77 4395.1,4227.77 4414.05,4246.72 v1(4493.52,4246.72)
  Sig2 w5.95: v1(4493.52,4246.72) 4493.52,4245.92 4509.2,4230.24 4532.49,4230.24 4547.64,4215.1 4804.22,4215.1 4873.11,4283.98 6066.82,4283.98 6110.96,4239.84 6110.96,4195.22 6072.48,4156.74 6053.82,4156.74 5972.05,4074.97 v1(5947.9,4074.97)
  Bottom Layer w6.7: v1(4493.52,4246.72) 4499.42,4240.82 4499.42,4239.84 4509.14,4230.12 4522.89,4230.12 4525.86,4233.08 R138.1@4537.25,4233.08 ; v1(5947.9,4074.97) 5947.9,4085.2 5957.35,4094.66 J11.31@6007.91,4094.66
AR_DP7: J11.33 R140.1 U2.L1 | length 2468.5
  Top Layer w6.7: U2.L1@4324.2,4188.37 4391.19,4188.37 4410.11,4207.29 4477.59,4207.29 4488.37,4196.51 4525.88,4196.51 4526.22,4196.85 4527.5,4196.85 4535.6,4204.95 4535.6,4227.14 v1(4516.02,4246.72)
  Sig2 w5.95: v1(4516.02,4246.72) 4560.49,4246.72 4567.71,4239.49 4811.79,4239.49 4868.42,4296.12 4900.64,4296.12 4903.83,4296.12 4908.62,4300.9 4908.62,4320.84 4913.4,4325.63 4919.78,4325.63 4924.56,4320.84 4924.56,4300.9 4929.35,4296.12 4935.73,4296.12 4940.51,4300.9 4940.51,4320.84 4945.3,4325.63 4951.67,4325.63 4956.46,4320.84 4956.46,4300.9 4961.24,4296.12 4967.62,4296.12 4972.41,4300.9 4972.41,4320.84 4977.19,4325.63 4983.57,4325.63 4988.35,4320.84 4988.35,4300.9 4993.14,4296.12 4999.52,4296.12 5004.3,4300.9 5004.3,4320.84 5009.08,4325.63 5015.46,4325.63 5020.25,4320.84 5020.25,4300.9 5025.03,4296.12 5031.41,4296.12 5036.19,4300.9 5036.19,4320.84 5040.98,4325.63 5047.36,4325.63 5052.14,4320.84 5052.14,4300.9 5056.92,4296.12 5063.88,4296.12 5831.7,4296.12 5852.35,4316.78 6051.34,4316.78 6122.86,4245.26 6122.86,4171.34 6067.59,4116.07 v1(6067.59,4071.83)
  Bottom Layer w5.95: J11.33@6007.91,4074.97 6064.44,4074.97 v1(6067.59,4071.83)
  Bottom Layer w6.7: v1(4516.02,4246.72) 4521.7,4252.4 R140.1@4537.25,4252.4
AR_GPIO_0: R66.1 RA5.8 U2.M2 | length 845.3
  Top Layer w6.7: v1(4276.95,4204.12) U2.M2@4292.7,4219.87
  Sig2 w5.95: v1(4276.95,4204.12) 4289.65,4191.42 4382.46,4191.42 4404.38,4213.33 4420.02,4213.33 4481.77,4275.08 4813.25,4275.08 4890.17,4352 4935.38,4352 4960.02,4376.64 v1(4960.02,4379.79)
  Bottom Layer w6.7: RA5.8@4952.34,4409.09 4952.34,4387.48 v1(4960.02,4379.79) 4962.26,4377.56 R66.1@4981.41,4377.56
AR_GPIO_1: R129.2 RA5.7 U2.L3 | length 1403.2
  Top Layer w6.7: v1(4245.46,4172.62) U2.L3@4261.2,4188.37 ; R129.2@5139.25,4519.45 5139.25,4410.27 v1(5160.84,4388.68)
  Sig2 w5.95: v1(4245.46,4172.62) 4380.49,4172.62 4409.3,4201.44 4424.95,4201.44 4486.7,4263.19 4818.67,4263.19 4893,4337.52 5109.69,4337.52 v1(5160.84,4388.68)
  Bottom Layer w6.7: RA5.7@4952.34,4424.84 4981.57,4424.84 5038,4368.41 5140.57,4368.41 v1@5158.08,4385.91
AR_GPIO_2: LD3.1 R115.1 RA5.6 U2.K3 | length 3948.2
  Top Layer w5.95: v1(6824.78,3961) R115.1@6844.78,3961
  Top Layer w6.7: v1(4245.46,4141.13) U2.K3@4261.2,4156.88 ; v1(4973.31,4455.06) 4979.31,4461.06 LD3.1@4979.31,4522.72
  Sig1 w5.95: v1(6226.68,4448.37) 6226.68,4360.49 6248.96,4338.21 6248.96,4253.51 6282.15,4220.31 6405.72,4220.31 6415.7,4210.33 6557.1,4210.33 6583.65,4236.89 6583.65,4276.96 6592.99,4286.29 6592.99,4369.07 6610.19,4386.28 6731.49,4386.28 6804.35,4313.42 6804.35,4076.19 6752.78,4024.62 6752.78,3956.54 6772.44,3936.88 6800.66,3936.88 v1(6824.78,3961)
  Sig2 w5.95: v1(4245.46,4141.13) 4243.4,4143.19 4227.54,4143.19 4212.53,4158.19 4212.53,4209.79 4223.33,4220.59 4394.81,4220.59 4406.98,4232.76 4422.62,4232.76 4476.84,4286.98 4808.33,4286.98 v1@4973.31,4451.96 ; v1(4973.31,4455.06) v1@4973.31,4451.96 ; v1(6226.68,4448.37) 6210.25,4431.94 6142.57,4431.94 6095.77,4478.74 5969.43,4478.74 5941.06,4450.38 5688.19,4450.38 5580.17,4342.36 5231.36,4342.36 5168.57,4405.15 5154.02,4405.15 5108.26,4359.39 5042.72,4359.39 4973.31,4428.79 v1@4973.31,4451.96
  Bottom Layer w6.7: RA5.6@4952.34,4440.59 4956.6,4440.59 v1@4972.18,4456.16
AR_HOSTINTR1: R3.1 R152.1 RA9.6 U2.B2 | length 2217.7
  Top Layer w6.7: U2.B2@4292.7,3904.91 v1(4308.45,3889.16)
  Sig1 w5.95: v1(4979.69,3994.63) 4979.69,3995.65 5022.55,4038.5 5078.71,4038.5 5118.81,4078.61 5228.77,4078.61 5315.76,4165.59 5315.76,4208.37 5189.21,4334.92 5189.21,4422.01 5289.86,4522.66 5497.63,4522.66 5667.88,4352.4 v1(5675.9,4352.4)
  Sig2 w5.95: v1(4308.45,3889.16) 4349.35,3889.16 4361.01,3877.5 4361.01,3850.85 4399.45,3812.41 4514.33,3812.41 4608.5,3906.58 4731.17,3906.58 4841.6,4017 4957.32,4017 v1(4979.69,3994.63)
  Bottom Layer w6.7: R3.1@4284.8,3889.16 v1(4308.45,3889.16) ; RA9.6@4960.68,3987.64 4969.78,3987.64 v1@4976.78,3994.63 ; v1(5675.9,4352.4) 5678.13,4350.18 R152.1@5678.13,4328.4
AR_LVDS_0_N: R149.1 RA6.7 U2.N1 | length 1347.9
  Top Layer w5.1: v1(4308.45,4267.11) U2.N1@4324.2,4251.36 ; v1@4955.46,4257.89 4951.31,4262.04 4951.31,4278.22 R149.1@4956.17,4283.07
  Sig1 w4.8: v1@4303.79,4271.41 4308.48,4266.72 4432.79,4266.72 4436.88,4262.64 4532.51,4262.64 4544.03,4251.11 4559.6,4251.11 4623.96,4186.74 4740.39,4186.74 4757.03,4170.1 4757.03,4122.55 4776.08,4103.49 4802.02,4103.49 4815.37,4116.84 4815.37,4160 4825.18,4169.81 4836.75,4169.81 4850.89,4155.66 4850.89,3980.23 4868.9,3962.22 4898.8,3962.22 4915.42,3978.85 4915.42,4207.44 4922.38,4214.4 4934.84,4214.4 4952.31,4231.87 4952.31,4254.74 v1@4955.46,4257.89
  Bottom Layer w5.1: RA6.7@4952.34,4292.08 4951.31,4291.06 4951.31,4262.04 v1@4955.46,4257.89
  other v1: 4954.45,4257.89
AR_LVDS_0_P: R148.1 RA6.8 U2.N2 | length 1378.2
  Top Layer w5.1: v1(4276.95,4267.11) U2.N2@4292.7,4251.36 ; R148.1@4932.76,4283.82 4937.61,4278.97 4937.61,4262.04 v1@4933.46,4257.89
  Sig1 w4.5: v1(4276.95,4267.11) 4276.95,4268.49 4291.33,4282.86 4314.97,4282.86 4315.02,4282.81 4329.69,4282.81 ; 4928.28,4230.4 4936.46,4238.59 4936.46,4254.89 v1@4933.46,4257.89
  Sig1 w4.8: 4315.11,4282.72 4443.56,4282.72 4447.64,4278.64 4539.13,4278.64 4550.66,4267.11 4566.22,4267.11 4630.59,4202.74 4747.02,4202.74 4773.03,4176.73 4773.03,4129.17 4782.71,4119.49 4795.39,4119.49 4799.37,4123.47 4799.37,4166.62 4813.87,4181.12 4818.56,4185.81 4843.37,4185.81 4866.89,4162.29 4866.89,3986.86 4875.53,3978.22 4892.17,3978.22 4899.42,3985.47 4899.42,4214.07 4915.75,4230.4 4928.28,4230.4
  Bottom Layer w5.1: v1@4933.46,4257.89 4924.29,4267.07 4924.29,4276.21 4929.55,4281.47 4933.77,4281.47 4936.59,4284.29 RA6.8@4936.59,4292.08
  other v1: 4932.45,4257.89
AR_LVDS_1_N: R147.1 RA7.5 U2.P1 | length 1514.7
  Top Layer w5.1: v1(4308.45,4298.61) U2.P1@4324.2,4282.86 ; v1@4996.38,4240.79 R147.1@5020,4240.79
  Sig1 w4.5: v1@4314.97,4298.61 4349.94,4298.61 ; v1@4315,4298.63 4461.96,4298.63
  Sig1 w4.8: 4349.94,4298.61 4462.36,4298.61 4474.02,4310.27 4585.93,4310.27 4594.45,4318.79 4713.9,4318.79 4723.1,4309.59 4723.1,4299.06 4718.12,4294.08 4625.17,4294.08 4609.92,4278.83 4609.92,4253.99 4639.23,4224.67 4762.1,4224.67 4775.28,4237.85 4775.28,4251.38 4783.96,4260.05 4801.76,4260.05 4810.09,4251.73 4810.09,4225.13 4825.25,4209.97 4864.39,4209.97 4883.45,4229.03 4883.45,4276.27 4904.75,4297.57 4989.83,4297.57 5016.62,4270.79 5016.62,4250.37 5014.7,4248.45 5008.13,4248.45 5005.1,4251.48 5005.1,4269.16 5002.59,4271.67 4996.91,4271.67 4994.13,4268.9 4994.13,4258.43 4980.76,4245.35 4980.76,4237.78 4985.99,4232.54 4992.41,4232.54 4995.28,4235.41 v1(4995.28,4239.89)
  Bottom Layer w5.1: RA7.5@4952.83,4236.76 4972.37,4236.76 4988.26,4252.65 4998.09,4252.65 5000.59,4250.16 5000.59,4245.19 v1(4995.28,4239.89)
AR_LVDS_1_P: R146.1 RA7.6 U2.P2 | length 1377.6
  Top Layer w5.1: v1(4276.95,4298.61) U2.P2@4292.7,4282.86 ; v1(4995.28,4215.89) 5001.84,4222.44 5015.35,4222.44 R146.1@5020,4217.79
  Sig1 w4.5: v1(4276.95,4298.61) 4292.7,4314.36 4314.97,4314.36 ; 4315,4314.33 4455.46,4314.33
  Sig1 w4.8: 4455.46,4314.33 4467.4,4326.27 4579.3,4326.27 4587.82,4334.79 4596.74,4334.79 4720.53,4334.79 4739.1,4316.22 4739.1,4292.43 4724.75,4278.08 4631.8,4278.08 4625.92,4272.2 4625.92,4260.61 4645.86,4240.67 4755.47,4240.67 4759.28,4244.48 4759.28,4258 4777.33,4276.05 4808.39,4276.05 4826.09,4258.35 4826.09,4231.76 4831.88,4225.97 4857.76,4225.97 4867.45,4235.66 4867.45,4282.9 4898.12,4313.57 4996.46,4313.57 5032.62,4277.41 5032.62,4236.67 5016.84,4220.89 5000.28,4220.89 v1(4995.28,4215.89)
  Bottom Layer w5.1: RA7.6@4953.34,4221.53 4953.86,4222.04 4984.13,4222.04 4990.28,4215.89 v1(4995.28,4215.89)
AR_LVDS_CLK_N: R145.1 RA7.7 U2.R2 | length 1444.6
  Top Layer w5.1: v1(4276.95,4330.1) U2.R2@4292.7,4314.36 ; v1(4988.85,4165.65) 4984.7,4169.8 4984.7,4177.53 4989.02,4181.85 5007.99,4181.85 5014.75,4175.09 5043.82,4175.09 R145.1@5047.69,4171.22
  Sig1 w4.5: v1(4276.95,4330.1) 4292.7,4345.85 4346.47,4345.85 4346.57,4345.95 4431.27,4345.95 4431.74,4346.42
  Sig1 w4.8: 4431.74,4346.42 4443.39,4358.07 4566.13,4358.07 4568.59,4360.53 4568.59,4394.28 4589.88,4415.56 4614.56,4415.56 4628.27,4401.85 4628.27,4379.9 4632.61,4375.56 4644.03,4375.56 4648.37,4379.9 4648.37,4401.85 4662.08,4415.56 4686.76,4415.56 4700.47,4401.85 4700.47,4379.9 4704.81,4375.56 4733.99,4375.56 4784.96,4324.59 4801.1,4324.59 4806.33,4329.83 4806.33,4382.57 4820.04,4396.28 4844.72,4396.28 4858.43,4382.57 4858.43,4360.8 4862.77,4356.46 5007.03,4356.46 5070.47,4293.03 5070.47,4195.36 5053.39,4178.29 4989.05,4178.29 4985.85,4175.09 4985.85,4168.65 v1(4988.85,4165.65)
  Bottom Layer w5.1: RA7.7@4953.34,4205.78 4954.37,4204.75 4970.09,4204.75 4984.7,4190.14 4984.7,4169.8 v1(4988.85,4165.65)
AR_LVDS_CLK_P: R144.1 RA7.8 U2.R1 | length 1469.1
  Top Layer w5.1: v1(4308.45,4330.1) U2.R1@4324.2,4314.36 ; v1(4966.85,4165.65) 4966.85,4179.06 4983.34,4195.55 5013.67,4195.55 5020.43,4188.79 5044.92,4188.79 R144.1@5048.79,4192.66
  Sig1 w4.8: v1(4308.45,4330.1) 4438.05,4330.1 4450.02,4342.07 4572.76,4342.07 4584.59,4353.9 4584.59,4387.65 4596.51,4399.56 4607.93,4399.56 4612.27,4395.23 4612.27,4373.28 4625.98,4359.56 4650.66,4359.56 4664.37,4373.28 4664.37,4395.23 4668.71,4399.56 4680.13,4399.56 4684.47,4395.23 4684.47,4373.28 4698.18,4359.56 4727.36,4359.56 4778.34,4308.59 4807.72,4308.59 4822.33,4323.2 4822.33,4343.44 4822.33,4354.17 4822.33,4375.94 4826.67,4380.28 4838.09,4380.28 4842.43,4375.94 4842.43,4354.17 4856.14,4340.46 5000.41,4340.46 5054.47,4286.4 5054.47,4201.99 5046.76,4194.29 4950.32,4194.29 4942.74,4186.71 4942.74,4170.03 4947.13,4165.65 v1(4966.85,4165.65)
  Bottom Layer w5.1: RA7.8@4954.37,4191.05 RA7.8@4953.34,4190.03 4961.5,4190.03 4964.41,4187.12 4964.41,4180.64 4961.93,4178.16 4945.93,4178.16 4940.41,4172.64 4940.41,4168.9 4943.66,4165.65 v1(4966.85,4165.65)
AR_LVDS_FRCLK_N: R143.1 RA8.5 U2.T2 | length 1399.8
  Top Layer w5.1: U2.T2@4292.7,4345.85 v1(4308.45,4361.6) ; v1(4966.85,4136.73) 4973.39,4130.19 4973.39,4117.17 R143.1@4967.77,4111.55
  Sig1 w4.5: 4324.2,4377.35 4351.72,4377.35
  Sig1 w4.8: v1(4308.45,4361.6) 4324.2,4377.35 ; 4351.72,4377.35 4369.12,4394.74 4369.12,4443.73 4409.95,4484.56 4491.96,4484.56 4518.26,4458.25 4824.18,4458.25 4848.55,4433.88 4983.07,4433.88 5109.57,4307.38 5109.57,4159.2 5038.01,4087.64 4991.11,4087.64 4971.7,4107.05 4971.7,4131.88 v1(4966.85,4136.73)
  Bottom Layer w5.1: RA8.5@4952.69,4119.49 4953.71,4118.47 4966.52,4118.47 4973,4124.95 4973,4130.58 v1(4966.85,4136.73)
AR_LVDS_FRCLK_P: R142.1 RA8.6 U2.T1 | length 1400.6
  Top Layer w5.1: U2.T1@4324.2,4345.85 v1(4339.94,4361.6) ; R142.1@4992.71,4111.55 4987.09,4117.17 4987.09,4130.97 v1(4992.85,4136.73)
  Sig1 w4.5: 4990.31,4111.06 4990.31,4118.68 4992.11,4120.47 5012.98,4120.47 5017.87,4125.35 5017.87,4133.27 5014.4,4136.73 v1(4992.85,4136.73)
  Sig1 w4.8: v1(4339.94,4361.6) 4358.6,4361.6 4385.12,4388.12 4385.12,4437.1 4416.57,4468.56 4485.33,4468.56 4511.64,4442.25 4817.55,4442.25 4841.92,4417.88 4976.45,4417.88 5038.46,4355.86 5093.66,4300.66 5093.66,4165.91 5031.38,4103.64 4997.74,4103.64 4990.31,4111.06
  Bottom Layer w5.1: RA8.6@4952.69,4103.74 4953.71,4104.77 4972.19,4104.77 4986.07,4118.64 5014.98,4118.64 5019.81,4123.47 5019.81,4132.27 5015.35,4136.73 v1(4992.85,4136.73)
AR_MCUCLKOUT: RA1.2 U2.V13 | length 912.6
  Top Layer w6.7: v1(3930.5,4424.59) U2.V13@3946.24,4408.84
  Sig2 w5.95: v1(3930.5,4424.59) 3928.19,4426.9 3928.19,4480.17 3985.52,4537.5 4468.02,4537.5 4518.57,4588.05 4655.12,4588.05 v1(4685.21,4618.14)
  Bottom Layer w6.7: RA1.2@4680.21,4600.58 4680.21,4613.14 v1(4685.21,4618.14)
AR_MISO1: R121.2 U2.D1 | length 3284.5
  Top Layer w6.7: v1(4308.45,3952.15) U2.D1@4324.2,3967.9 ; v1@6621.04,4333.23 R121.2@6639.03,4333.23
  Sig2 w4.5: v1(4308.45,3952.15) 4324.2,3936.4 4354.1,3936.4 4354.83,3937.13
  Sig2 w5.95: 4354.83,3937.13 4361.44,3937.13 4372.91,3925.66 4372.91,3855.77 4404.38,3824.3 4509.4,3824.3 4603.57,3918.47 4726.25,3918.47 4836.67,4028.89 4979.54,4028.89 4996.01,4012.42 4996.01,3972.76 5043.76,3925.01 5156.99,3925.01 5200.46,3881.53 5200.46,3729.32 5213.74,3716.04 5717.64,3716.04 5766.81,3765.21 5867.81,3765.21 5925.35,3707.67 6230.52,3707.67 6249.35,3726.5 6249.35,3783.85 6353.24,3887.74 6389.62,3887.74 6411.96,3910.08 6475.27,3910.08 6515.07,3949.88 6515.07,4102.64 6544.36,4131.93 6564.41,4131.93 6595.55,4163.07 6595.55,4311.03 6617.52,4333 v1(6618.45,4333)
AR_MOSI1: R128.2 U2.F2 | length 3442.7
  Top Layer w6.7: v1(4276.95,4015.14) U2.F2@4292.7,4030.89 ; v1(6617.81,4271) 6619.56,4269.25 6670.56,4269.25 6685.71,4254.1 R128.2@6685.71,4240.71 6685.71,4167.71 6674.74,4156.74 v1(6671.76,4156.74)
  Sig1 w4.5: 4298.2,4030.13 4298.96,4030.89 4315.78,4030.89
  Sig1 w5.5: v1(4276.95,4015.14) 4281.75,4019.94 4288.01,4019.94 4298.2,4030.13
  Sig1 w5.95: 4315.78,4030.89 4316.36,4030.32 4316.57,4030.32 ; 4316,4030.89 4316.57,4030.32 ; v1(6671.76,4156.74) 6707.37,4156.74 6713.44,4150.66 6713.44,4056.18 6695.34,4038.07 6650.14,4038.07 6645.51,4033.44 6645.51,4022.15 6658.05,4009.61 6658.05,4000.78 6645.8,3988.53 6265.17,3988.53 6230.16,3953.52 6230.16,3834.57 6224.41,3828.82 6224.41,3801.5 6161.2,3738.29 5837.07,3738.29 5802.08,3773.28 5802.08,3848.99 5726.34,3924.73 5706.97,3924.73 5659.85,3877.61 5564.53,3877.61 5407.56,3720.64 5169.06,3720.64 5140.34,3749.37 5140.34,3803.39 5082.45,3861.27 5033.83,3861.27 5017.76,3877.34 4960,3877.34 4945.78,3863.12 4647.49,3863.12 4616.86,3832.48 4590.58,3832.48 4482.26,3940.8 4447.59,3940.8 4447.59,3941.6 4366.75,4022.44 4324.45,4022.44 4316.57,4030.32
